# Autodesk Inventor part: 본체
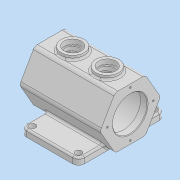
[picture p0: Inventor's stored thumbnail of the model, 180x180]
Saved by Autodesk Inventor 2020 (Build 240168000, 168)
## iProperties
Created: 2021-06
Part Number: 본체
Material: 일반
Document SubType Name: Modeling
Designer: MIRAE
Density: 1 g/cm^3
Appearance: 기본값
Author: MIRAE
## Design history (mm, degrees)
sketch "스케치1"
  geometry: L1 (-50, -75)-(50, -75); L2 (50, -75)-(50, 75); L3 (50, 75)-(-50, 75); L4 (-50, 75)-(-50, -75); L5 (-50, -75)-(50, 75); L6 (50, -75)-(-50, 75); 1 further point
  constraints: 12 end point, 2 midpoint, 2 parallel, 1 horizontal, 1 perpendicular
  dimensions: "d0" = 100 distance of L2.end L3.end; "d1" = 150 distance of L1.end L2.end
extrude "돌출1" new body sketch "스케치1" distance "d2" = 12; taper "d3" = 0 deg
node "작업 평면2"
sketch "스케치6" dims "d28" = 105
  geometry: L1 (-50, 127.5)-(-4.534, 101.25); L2 (-4.534, 101.25)-(-4.534, 48.75); L3 (-4.534, 48.75)-(-50, 22.5); L4 (-50, 22.5)-(-95.466, 48.75); L5 (-95.466, 48.75)-(-95.466, 101.25); L6 (-95.466, 101.25)-(-50, 127.5); L7 (-50, 22.5)-(-50, 127.5); L8 (0, 0)-(0, 150) reference; L9 (0, 0)-(-12, 0) reference; 3 further points
  constraints: 14 end point, 1 coincident, 1 vertical, 16 other
  dimensions: "d29" = 50 distance between parallel lines of L8 L7; "d30" = 75 distance from line of L9 point (-50, 75)
extrude "돌출5" join sketch "스케치6" distance "d31" = 140; taper "d32" = 0 deg
sketch "스케치7"
  geometry: L1 (75, 50)-(75, 4.534) reference; L2 (75, 50)-(63, 50); L3 (63, 50)-(63, 80); L4 (63, 80)-(75, 80); L5 (75, 80)-(75, 50); L6 (63, 50)-(-53, 50); L7 (-53, 50)-(-53, 87.5); L8 (-53, 87.5)-(63, 87.5); L9 (63, 87.5)-(63, 50); L10 (-65, 50)-(-65, 95.466) reference; L11 (-53, 50)-(-65, 50); L12 (-65, 50)-(-65, 80); L13 (-65, 80)-(-53, 80); L14 (-53, 80)-(-53, 50); 4 further points
  constraints: 24 end point, 6 parallel, 3 horizontal, 3 perpendicular, 2 point on line
  dimensions: "d33" = 12 distance of L12.end L13.end; "d34" = 12 distance of L3.end L4.end; "d35" = 60 diameter of L4 L2; "d36" = 75 diameter of L8 L6
revolve "회전2" sketch "스케치7" stored, may be unused: angle "d37" = 90 deg
node "작업 평면3"
sketch "스케치8"
  geometry: L1 (-75, -26.25)-(-75, 26.25) reference; C1 r 20 at (-35, 0); C2 r 20 at (25, 0); 1 further point
  constraints: 2 centre point
  dimensions: "d39" = 40 diameter of C1; "d40" = 40 diameter of C2; "d41" = 40 distance from line of L1 C1.centre; "d42" = 60 distance of C1.centre C2.centre
extrude "돌출6" join sketch "스케치8" stored distance "d43" = 140; taper "d44" = 0 deg
sketch "스케치9" dims "d33" = 12, "d34" = 12, "d35" = 60, "d36" = 75
  geometry: C1 r 20 at (0, 0) reference; C2 r 20 at (60, 0) reference; 3 further points
  constraints: 2 coincident
hole "구멍1" sketch "스케치9" at (0, 0), (60, 0) diameter "d45" = 25; stored, may be unused: countersink angle "d49" = 90 deg, drill point angle "d51" = 118 deg; dims "d46" = 6, "d47" = 30, "d48" = 8, "d50" = 8
fillet "모깎기1" dims "d52" = 5
sketch "스케치10"
  geometry: C1 r 30 at (-50, 75) reference; 2 further points
  dimensions: "d53" = 40 distance of C1.centre point (-90, 75); "d54" = 0 vertical distance of point (-90, 75) C1.centre
hole "구멍2" sketch "스케치10" at (-90, 75) diameter "d55" = 3.242; stored, may be unused: countersink angle "d59" = 90 deg, drill point angle "d61" = 118 deg; dims "d56" = 8, "d57" = 30, "d58" = 8, "d60" = 10
sketch "스케치11"
  geometry: L1 (50, 75)-(102.5, 75); L2 (50, 75)-(78.284, 103.284); L3 (102.5, 55)-(102.5, 95) reference; C1 r 30 at (50, 75) reference; 1 further point
  constraints: 4 end point, 1 horizontal, 1 midpoint
  dimensions: "d65" = 40 distance of L1.start L2.end; "d66" = 45 deg angle of L1 L2
hole "구멍3" sketch "스케치11" at (78.284, 103.284) diameter "d67" = 3.242; stored, may be unused: countersink angle "d71" = 90 deg, drill point angle "d73" = 118 deg; dims "d68" = 8, "d69" = 30, "d70" = 8, "d72" = 10
fillet "모깎기2" dims "d77" = 10
sketch "스케치12"
  geometry: A1 r 10 centre (-40, -65) between (-50, -65) and (-40, -75) reference; A2 r 10 centre (-40, 65) between (-40, 75) and (-50, 65) reference; A3 r 10 centre (40, 65) between (50, 65) and (40, 75) reference; A4 r 10 centre (40, -65) between (40, -75) and (50, -65) reference; 5 further points
  constraints: 4 coincident
hole "구멍4" sketch "스케치12" at (-40, -65), (-40, 65), (40, 65), (40, -65) diameter "d78" = 11; stored, may be unused: countersink angle "d82" = 90 deg, drill point angle "d84" = 118 deg; dims "d79" = 8, "d80" = 30, "d81" = 8, "d83" = 10
sketch "스케치13"
  geometry: L1 (-50, 65)-(-50, 30.561) reference; L2 (40, 75)-(-40, 75) reference; 2 further points
  constraints: 1 other
  dimensions: "d85" = 50 distance from line of L1 point (0, 61); "d86" = 14 distance from line of L2 point (0, 61)
feature "엠보싱1" sketch "스케치13" dims "d0" = 100, "d1" = 150, "d87" = 0.5, "d88" = 0
fillet "모깎기3" dims "d89" = 8
fillet "모깎기4" dims "d90" = 3
fillet "모깎기5" dims "d91" = 3
fillet "모깎기6" dims "d92" = 3
fillet "모깎기7" dims "d93" = 3
chamfer "모따기1" distance "d94" = 1; stored, may be unused: second distance "d95" = 2, angle "d96" = 45 deg
sketch "스케치14"
  geometry: L1 (-119.902, 75)-(-26.513, 75); L2 (-26.513, 75)-(-26.513, 5.881); L3 (-26.513, 5.881)-(-119.902, 5.881); L4 (-119.902, 5.881)-(-119.902, 75); 1 further point
  constraints: 8 end point, 2 parallel, 1 horizontal, 1 perpendicular
extrude "돌출7" cut sketch "스케치14" extent not by distance; stored distance "d97" = 0; taper "d98" = 0 deg
node "솔리드1"
pattern_circular "원형 패턴1" dims angle "d63" = 360 deg
pattern_circular "원형 패턴2" dims angle "d75" = 360 deg
feature "A9D066F2-1C7D-4E18-AEED-F7BC21143FA4" dims "d78" = 11, "d79" = 8, "d80" = 30, "d81" = 8, "d82" = 90 deg, "d83" = 10, "d84" = 118 deg
other parameters: "d27" = 15, "d38" = 102.5
